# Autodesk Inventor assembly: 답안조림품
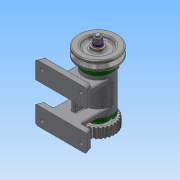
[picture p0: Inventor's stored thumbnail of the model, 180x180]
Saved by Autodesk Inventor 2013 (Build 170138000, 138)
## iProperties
Created: 2016-07
Part Number: 답안조림품
Document SubType Name: Assembly
Designer: Administrator
Author: Administrator
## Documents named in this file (16)
- C:\Users\Administrator\Desktop\460708V1017\답안조림품.iam
- C:\Users\Administrator\Desktop\460708V1017\본체.ipt
- C:\Users\Administrator\Desktop\460708V1017\V벨트풀리.ipt
- C:\Users\Administrator\Desktop\460708V1017\너트 M 8.ipt
- C:\Users\Administrator\Desktop\460708V1017\니플 M 6 x 0.75.ipt
- C:\Users\Administrator\Desktop\460708V1017\베어링 15 x 32 x 9.ipt
- C:\Users\Administrator\Desktop\460708V1017\볼트 M 6 x 8.ipt
- C:\Users\Administrator\Desktop\460708V1017\볼트 M4 x 12.ipt
- C:\Users\Administrator\Desktop\460708V1017\스퍼기어.ipt
- C:\Users\Administrator\Desktop\460708V1017\스프링와셔 8.ipt
- C:\Users\Administrator\Desktop\460708V1017\오일 실 15 25 7.ipt
- C:\Users\Administrator\Desktop\460708V1017\와셔 6x11.5.ipt
- C:\Users\Administrator\Desktop\460708V1017\와셔 8x17.ipt
- C:\Users\Administrator\Desktop\460708V1017\축.ipt
- C:\Users\Administrator\Desktop\460708V1017\커버.ipt
- C:\Users\Administrator\Desktop\460708V1017\키 3 x 3 x 12.ipt
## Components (11 placed, 3 different names)
1. V벨트풀리:1
2. KS B 2023 6002 - 15 x 32 x 9:1
3. KS B 2023 6002 - 15 x 32 x 9:2
4. ISO 4762 M4 x 12:1
5. ISO 4762 M4 x 12:3
6. ISO 4762 M4 x 12:4
7. ISO 4762 M4 x 12:5
8. ISO 4762 M4 x 12:2
9. ISO 4762 M4 x 12:6
10. ISO 4762 M4 x 12:7
11. ISO 4762 M4 x 12:8
